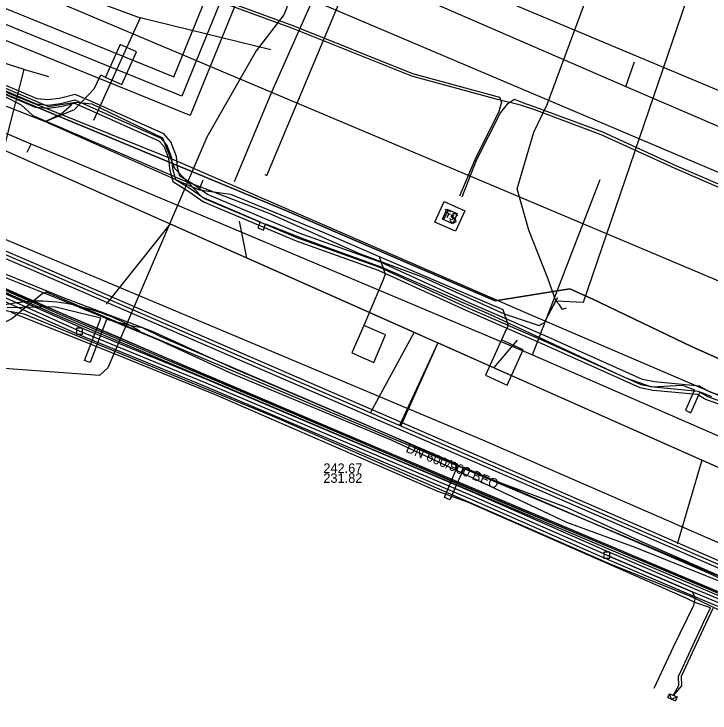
# Model space of a CAD drawing. Extents: x -596024 to -594475, y -1163820 to -1161957.
# Drawn here: x -594674.7 to -594616.3, y -1162272.9 to -1162214.2 of the extents above; entities that cross this region are included whole.
import ezdxf

# ---------------------------------------------------------------- set-up
doc = ezdxf.new("R2010")
doc.units = 0
for name, color, linetype in [('25', 7, 'Continuous'), ('31', 7, 'Continuous'), ('Level 1', 7, 'Continuous'), ('Vrstva 1', 7, 'Continuous'), ('Vrstva 10', 7, 'Continuous'), ('Vrstva 11', 7, 'Continuous'), ('Vrstva 12', 7, 'Continuous'), ('Vrstva 13', 7, 'Continuous'), ('Vrstva 19', 7, 'Continuous'), ('Vrstva 29', 7, 'Continuous'), ('Vrstva 30', 7, 'Continuous'), ('Vrstva 42', 7, 'Continuous'), ('Vrstva 43', 7, 'Continuous'), ('Vrstva 44', 7, 'Continuous'), ('Vrstva 45', 7, 'Continuous'), ('Vrstva 55', 7, 'Continuous'), ('Vrstva 58', 7, 'Continuous'), ('Vrstva 9', 7, 'Continuous')]:
    doc.layers.add(name, color=color, linetype=linetype)

# ---------------------------------------------------------------- blocks, each defined once
blk = doc.blocks.new('NN640')
at = {"layer": '25'}
for points in [[(-1.89, 1.889), (1.889, 1.889)], [(-1.89, -1.89), (-1.89, 1.889)], [(1.889, 1.889), (1.889, -1.89)], [(-1.26, 0.787), (-0.221, 0.787)], [(-0.725, 0.787), (-0.725, -0.788)], [(1.197, 0.661), (0.945, 0.787), (0.661, 0.787), (0.409, 0.661), (0.283, 0.472), (0.283, 0.409), (0.409, 0.22), (1.133, -0.158), (1.259, -0.316), (1.259, -0.473), (1.133, -0.662), (0.913, -0.788), (0.629, -0.788), (0.503, -0.725), (0.283, -0.599)], [(1.889, -1.89), (-1.89, -1.89)]]:
    blk.add_lwpolyline(points, dxfattribs=at)
blk = doc.blocks.new('NN630')
at = {"layer": '31'}
for points in [[(-0.003, -0.7), (-0.703, 0)], [(-0.703, -0.7), (-0.703, 0), (0.697, 0), (0.697, -0.7)], [(-0.003, -0.7), (0.697, 0)], [(-0.703, -0.7), (0.697, -0.7)]]:
    blk.add_lwpolyline(points, dxfattribs=at)
blk = doc.blocks.new('VN640')
at = {"layer": '25'}
for points in [[(-1.89, 1.889), (1.889, 1.889)], [(-1.89, -1.89), (-1.89, 1.889)], [(-1.26, 0.787), (-0.221, 0.787)], [(-0.725, 0.787), (-0.725, -0.788)], [(1.197, 0.661), (0.945, 0.787), (0.661, 0.787), (0.409, 0.661), (0.283, 0.472), (0.283, 0.409), (0.409, 0.22), (1.133, -0.158), (1.259, -0.316), (1.259, -0.473), (1.133, -0.662), (0.913, -0.788), (0.629, -0.788), (0.503, -0.725), (0.283, -0.599)], [(1.889, 1.889), (1.889, -1.89)], [(1.889, -1.89), (-1.89, -1.89)]]:
    blk.add_lwpolyline(points, dxfattribs=at)

msp = doc.modelspace()

# ---------------------------------------------------------------- linework, layer by layer
at = {"layer": 'Level 1'}
for points in [[(-594750.45, -1162195.55), (-594709.77, -1162211.75), (-594681.66, -1162222.95), (-594639.16, -1162241.84), (-594604.2, -1162257.38), (-594561.16, -1162275.84)], [(-594655.18, -1162234.72), (-594655.8, -1162231.63)], [(-594661.62, -1162231.86), (-594666.98, -1162238.6)], [(-594641.16, -1162240.95), (-594644.83, -1162247.74)], [(-594634.45, -1162243.94), (-594632.48, -1162241.63)], [(-594639.16, -1162241.84), (-594642.26, -1162248.81)], [(-594617, -1162251.69), (-594619.08, -1162258.74)]]:
    msp.add_lwpolyline(points, dxfattribs=at)
at = {"layer": 'Vrstva 1'}
msp.add_line((-594639.16, -1162241.84), (-594642.37, -1162248.79), dxfattribs=at)
for points in [[(-594681.66, -1162222.95), (-594661.62, -1162231.86), (-594655.18, -1162234.72), (-594641.16, -1162240.95), (-594639.16, -1162241.84)], [(-594604.2, -1162257.38), (-594609.94, -1162254.83), (-594617, -1162251.69), (-594634.45, -1162243.94), (-594639.16, -1162241.84)]]:
    msp.add_lwpolyline(points, dxfattribs=at)
at = {"layer": 'Vrstva 10'}
for p, q in [((-594642.25, -1162248.515), (-594610.431, -1162262.393)), ((-594610.671, -1162262.943), (-594642.49, -1162249.065))]:
    msp.add_line(p, q, dxfattribs=at)
for points in [[(-594718.121, -1162215.685), (-594682.698, -1162231.026), (-594673.018, -1162235.167), (-594642.251, -1162248.515)], [(-594642.489, -1162249.065), (-594673.256, -1162235.718), (-594682.935, -1162231.577), (-594718.359, -1162216.235)], [(-594669.097, -1162240.596), (-594676.92, -1162237.095), (-594687.944, -1162232.423), (-594698.459, -1162228.081), (-594703.881, -1162225.994), (-594707.851, -1162224.099), (-594708.531, -1162223.765)], [(-594669.343, -1162241.144), (-594677.16, -1162237.645), (-594688.176, -1162232.977), (-594698.681, -1162228.639), (-594704.119, -1162226.546), (-594708.109, -1162224.641), (-594708.769, -1162224.315)], [(-594624.869, -1162259.405), (-594636.251, -1162254.395), (-594658.494, -1162244.943), (-594669.106, -1162240.592)], [(-594625.111, -1162259.955), (-594636.489, -1162254.945), (-594658.726, -1162245.497), (-594669.334, -1162241.148)], [(-594580.255, -1162278.093), (-594603.815, -1162268.273), (-594617.713, -1162262.474), (-594624.153, -1162259.704), (-594624.875, -1162259.403)], [(-594580.485, -1162278.647), (-594604.045, -1162268.827), (-594617.947, -1162263.026), (-594624.387, -1162260.256), (-594625.105, -1162259.957)]]:
    msp.add_lwpolyline(points, dxfattribs=at)
at = {"layer": 'Vrstva 11'}
for points in [[(-594669.47, -1162241.12), (-594668.97, -1162241.12), (-594668.97, -1162240.62), (-594669.47, -1162240.62)], [(-594625.24, -1162259.93), (-594624.74, -1162259.93), (-594624.74, -1162259.43), (-594625.24, -1162259.43)]]:
    msp.add_lwpolyline(points, close=True, dxfattribs=at)
at = {"layer": 'Vrstva 12'}
for points in [[(-594629.27, -1162238.33), (-594629.91, -1162236.5), (-594631.53, -1162232.4), (-594632.5, -1162228.92), (-594631.11, -1162224.16), (-594630, -1162221.85), (-594628.4, -1162217.53), (-594623.66, -1162204.74), (-594619.72, -1162192.17), (-594619.95, -1162191.15), (-594620.564, -1162190.795), (-594621.931, -1162190.178)], [(-594665.75, -1162215.48), (-594673.84, -1162212.04)], [(-594629.27, -1162238.33), (-594626.94, -1162238.42), (-594618.29, -1162213.11)], [(-594701.93, -1162231.57), (-594700.22, -1162232.12), (-594699.53, -1162232.3), (-594698.85, -1162231.48), (-594698.82, -1162230.28), (-594692.89, -1162215.39), (-594692.41, -1162214.76), (-594691.46, -1162214.73), (-594685.17, -1162217.2), (-594675.66, -1162221.09), (-594674.13, -1162221.87), (-594673.14, -1162222.77), (-594660.42, -1162228.26), (-594659.07, -1162228.75), (-594653.33, -1162230.97), (-594645.81, -1162234.32), (-594640.49, -1162236.32), (-594633.61, -1162239.41), (-594630.67, -1162240.39), (-594630.22, -1162240.14), (-594629.84, -1162239.45)], [(-594701.93, -1162231.57), (-594700.22, -1162232.12), (-594699.53, -1162232.3), (-594698.85, -1162231.48), (-594698.82, -1162230.28), (-594692.89, -1162215.39), (-594692.41, -1162214.76), (-594691.46, -1162214.73), (-594685.17, -1162217.2), (-594675.66, -1162221.09), (-594674.13, -1162221.87), (-594673.14, -1162222.77), (-594660.42, -1162228.26), (-594659.07, -1162228.75), (-594653.33, -1162230.97), (-594645.81, -1162234.32), (-594640.49, -1162236.32), (-594633.61, -1162239.41), (-594630.67, -1162240.39), (-594630.22, -1162240.14), (-594629.84, -1162239.45)], [(-594584.85, -1162250), (-594590.2, -1162247.4), (-594665.75, -1162215.48)], [(-594687.5, -1162228.11), (-594635.41, -1162250)], [(-594603.93, -1162268.55), (-594617.83, -1162262.75), (-594624.27, -1162259.98), (-594624.99, -1162259.68), (-594636.37, -1162254.67), (-594658.61, -1162245.22), (-594669.22, -1162240.87), (-594677.04, -1162237.37)], [(-594629.84, -1162239.45), (-594629.1, -1162238.04)], [(-594629.84, -1162239.45), (-594629.27, -1162238.33)], [(-594628.4, -1162238.935), (-594628.69, -1162239.05), (-594628.96, -1162238.67), (-594629.27, -1162238.33)], [(-594635.41, -1162250), (-594584.42, -1162272.21)], [(-594624.99, -1162259.68), (-594624.27, -1162259.98), (-594617.83, -1162262.75), (-594617.57, -1162263.22), (-594617.72, -1162263.9), (-594619.43, -1162267.41), (-594621.03, -1162270.87)], [(-594617.83, -1162262.75), (-594617.57, -1162263.22), (-594617.72, -1162263.9), (-594619.43, -1162267.41), (-594621.03, -1162270.87)]]:
    msp.add_lwpolyline(points, dxfattribs=at)
at = {"layer": 'Vrstva 13'}
for p, q in [((-594649.599, -1162213.102), (-594475.47, -1162287.071)), ((-594673.314, -1162225.133), (-594673.46, -1162225.47)), ((-594673.46, -1162225.47), (-594673.646, -1162225.878)), ((-594631.22, -1162242.86), (-594625.533, -1162228.125))]:
    msp.add_line(p, q, dxfattribs=at)
for points in [[(-594836.23, -1162155.443), (-594836.196, -1162155.782), (-594816.247, -1162164.384), (-594814.935, -1162164.957), (-594803.879, -1162169.64), (-594755.473, -1162190.086), (-594744.01, -1162194.87), (-594731.121, -1162200.339), (-594730.015, -1162200.811), (-594704.47, -1162211.75), (-594699.45, -1162213.94), (-594673.314, -1162225.133)], [(-594653.687, -1162227.711), (-594653.503, -1162227.79), (-594646.352, -1162210.669), (-594640.557, -1162197.047)], [(-594654.732, -1162204.193), (-594543.215, -1162251.024), (-594524.873, -1162258.743), (-594475.47, -1162279.606)], [(-594651.55, -1162212.94), (-594652.09, -1162214.3), (-594654.4, -1162217.32), (-594658.53, -1162224.58), (-594666.86, -1162243.95), (-594667.56, -1162244.58), (-594677.47, -1162243.87), (-594678.66, -1162244.27), (-594679.14, -1162245.09), (-594685.17, -1162257.8), (-594694.88, -1162278.83), (-594696.109, -1162281.678), (-594702.06, -1162295.48), (-594710.48, -1162314.62), (-594714.12, -1162323.47), (-594715.655, -1162327.014), (-594723.77, -1162345.59), (-594733.52, -1162367.83)], [(-594673.314, -1162225.133), (-594670.332, -1162226.359), (-594656.079, -1162232.372), (-594631.22, -1162242.86), (-594605.499, -1162254.07), (-594601.67, -1162255.71)]]:
    msp.add_lwpolyline(points, dxfattribs=at)
at = {"layer": 'Vrstva 19'}
for points in [[(-594695.25, -1162276.17), (-594690.21, -1162265.28), (-594680.2, -1162243.33), (-594679.351, -1162240.241), (-594678.82, -1162238.33), (-594678.078, -1162235.421), (-594674.9, -1162222.97), (-594673.86, -1162218.9), (-594682.15, -1162216.27), (-594693.73, -1162211.66), (-594707.83, -1162205.54), (-594713.34, -1162203.16), (-594714.6, -1162202.61), (-594730.47, -1162196.31), (-594740.5, -1162192.55), (-594751.07, -1162187.95), (-594753.63, -1162189.06), (-594775.09, -1162179.85), (-594776.07, -1162176.84), (-594793.1, -1162168.81), (-594802.09, -1162164.76), (-594816.08, -1162158.49), (-594834.13, -1162150.42), (-594853.67, -1162141.96)], [(-594673.04, -1162199.27), (-594648.07, -1162209.58), (-594623.39, -1162220.33), (-594563.61, -1162246.04), (-594512.61, -1162267.89), (-594494.198, -1162275.805), (-594475.47, -1162283.856)], [(-594648.07, -1162209.58), (-594649.73, -1162213.19), (-594653.1, -1162220.75), (-594656.24, -1162228.33)], [(-594623.39, -1162220.33), (-594622.82, -1162218.73), (-594622.66, -1162218.26)], [(-594673.86, -1162218.9), (-594673.57, -1162218.98)], [(-594673.57, -1162218.98), (-594672.59, -1162219.27), (-594671.82, -1162219.49)], [(-594672.02, -1162237.58), (-594672.39, -1162237.76), (-594674.91, -1162239.83), (-594676.98, -1162240.84), (-594678.73, -1162240.33), (-594678.81, -1162240.31), (-594679.02, -1162240.26), (-594679.43, -1162240.18), (-594679.63, -1162240.15), (-594679.77, -1162240.12), (-594682.47, -1162239.25), (-594684.29, -1162236.54), (-594684.66, -1162235.21), (-594685.53, -1162232.03), (-594685.55, -1162231.56)], [(-594475.47, -1162321.138), (-594483.988, -1162317.438), (-594524.1, -1162300.42), (-594530.74, -1162297.58), (-594538.63, -1162294.19), (-594559.12, -1162285.38), (-594563.88, -1162283.33), (-594564.7, -1162283.08), (-594583.65, -1162275.06), (-594601.81, -1162267.29), (-594608.3, -1162264.51), (-594626.74, -1162256.75), (-594672.02, -1162237.58)]]:
    msp.add_lwpolyline(points, dxfattribs=at)
at = {"layer": 'Vrstva 29'}
msp.add_lwpolyline([(-594527.721, -1162116.547), (-594550.035, -1162144.733), (-594618.49, -1162117.698), (-594660.636, -1162221.142), (-594706.437, -1162202.481)], dxfattribs=at)
at = {"layer": 'Vrstva 30'}
for points in [[(-594706.74, -1162201.008), (-594661.322, -1162219.513), (-594619.181, -1162116.081), (-594550.439, -1162143.229), (-594528.701, -1162115.771)], [(-594526.741, -1162117.323), (-594549.631, -1162146.237), (-594617.799, -1162119.315), (-594659.95, -1162222.771), (-594706.133, -1162203.955)]]:
    msp.add_lwpolyline(points, dxfattribs=at)
at = {"layer": 'Vrstva 42'}
for points in [[(-594841.22, -1162164.89), (-594841.55, -1162165.818), (-594823.941, -1162173.342), (-594805.527, -1162181.255), (-594786.096, -1162189.732), (-594763.998, -1162199.133), (-594752.438, -1162204.617), (-594739.102, -1162210.309), (-594723.16, -1162216.972), (-594709.798, -1162222.556), (-594699.416, -1162226.808), (-594686.936, -1162232.243), (-594670.535, -1162239.442), (-594642.912, -1162251.21), (-594626.307, -1162258.207), (-594595.818, -1162271.123), (-594582.146, -1162276.922), (-594568.678, -1162282.65), (-594548.298, -1162291.531), (-594530.464, -1162298.451), (-594511.972, -1162306.232), (-594493.611, -1162313.902), (-594475.47, -1162321.871)], [(-594805, -1162180.3), (-594805.561, -1162181.567), (-594805.473, -1162181.605), (-594786.214, -1162190.008), (-594764.122, -1162199.407), (-594752.562, -1162204.891), (-594739.218, -1162210.585), (-594723.276, -1162217.248), (-594709.912, -1162222.834), (-594699.532, -1162227.084), (-594687.056, -1162232.517), (-594670.655, -1162239.718), (-594643.03, -1162251.486), (-594626.423, -1162258.483), (-594595.936, -1162271.399), (-594582.264, -1162277.198), (-594568.796, -1162282.926), (-594548.412, -1162291.809), (-594530.576, -1162298.729), (-594512.088, -1162306.508), (-594493.729, -1162314.178), (-594475.47, -1162322.199)], [(-594475.47, -1162322.035), (-594492.486, -1162314.56), (-594509.999, -1162307.221), (-594528.715, -1162299.349), (-594548.355, -1162291.67), (-594568.737, -1162282.788), (-594582.205, -1162277.06), (-594595.877, -1162271.261), (-594626.365, -1162258.345), (-594642.971, -1162251.348), (-594670.595, -1162239.58), (-594686.996, -1162232.38), (-594699.474, -1162226.946), (-594709.855, -1162222.695), (-594723.218, -1162217.11), (-594739.16, -1162210.447), (-594752.5, -1162204.754), (-594764.06, -1162199.27), (-594786.155, -1162189.87), (-594805.5, -1162181.43)], [(-594615.74, -1162262.79), (-594624.65, -1162259.07), (-594637.95, -1162253.48), (-594653.13, -1162246.96), (-594666.17, -1162241.28), (-594679.92, -1162235.52), (-594687.43, -1162232.45), (-594694.39, -1162229.4), (-594701, -1162226.48), (-594711.77, -1162221.9), (-594718.09, -1162219.27), (-594728.65, -1162214.76), (-594737.08, -1162211.18), (-594746.93, -1162206.99), (-594753.92, -1162203.71), (-594761.99, -1162200.35), (-594768.71, -1162197.49), (-594777.63, -1162193.65), (-594785.3, -1162190.25), (-594792.89, -1162187), (-594796.23, -1162185.84), (-594796.51, -1162185.77), (-594796.81, -1162185.85)], [(-594667.01, -1162219.57), (-594665.682, -1162220.163), (-594664.458, -1162217.424), (-594665.828, -1162216.812), (-594667.052, -1162219.551)], [(-594672.114, -1162223.265), (-594669.65, -1162222.26), (-594667.99, -1162220.51), (-594667.45, -1162219.35), (-594667.01, -1162219.57)], [(-594679.89, -1162220.2), (-594674.37, -1162222.37), (-594672.114, -1162223.265)], [(-594672.114, -1162223.265), (-594670.76, -1162222.61), (-594669.89, -1162221.86)], [(-594672.114, -1162223.265), (-594660.02, -1162228.63), (-594659.18, -1162228.99), (-594656.56, -1162229.37), (-594648.72, -1162232.59), (-594644.08, -1162234.6)], [(-594659.18, -1162228.99), (-594658.85, -1162228.16)], [(-594644.08, -1162234.6), (-594643.57, -1162236.08), (-594643.76, -1162236.56)], [(-594644.08, -1162234.6), (-594633.71, -1162239.06)], [(-594643.76, -1162236.56), (-594645.383, -1162240.399), (-594646.369, -1162242.696), (-594644.531, -1162243.485), (-594643.545, -1162241.188), (-594645.383, -1162240.399)], [(-594616.092, -1162264.165), (-594616.71, -1162265.465), (-594618.755, -1162269.87), (-594618.731, -1162270.634), (-594619.409, -1162271.444), (-594618.942, -1162270.611), (-594618.967, -1162269.852), (-594616.892, -1162265.379), (-594616.277, -1162264.09), (-594617.599, -1162263.644), (-594618.337, -1162263.293), (-594636.59, -1162255.243), (-594639.149, -1162254.338), (-594657.807, -1162246.223), (-594668.713, -1162241.784), (-594674.966, -1162239.293)], [(-594633.71, -1162239.06), (-594633.27, -1162240.4), (-594633.53, -1162240.97)], [(-594633.53, -1162240.97), (-594633.821, -1162241.605), (-594635.17, -1162244.562), (-594633.35, -1162245.392), (-594632.001, -1162242.435), (-594633.821, -1162241.605)]]:
    msp.add_lwpolyline(points, dxfattribs=at)
for centre, radius, start, end in [((-594672.585, -1162251.354), 13.003, 81.93145, 108.86849), ((-594673.743, -1162257.133), 18.89, 59.48106, 80.91506)]:
    msp.add_arc(centre, radius, start, end, dxfattribs=at)
at = {"layer": 'Vrstva 44'}
for points in [[(-594615.489, -1162264.329), (-594617.876, -1162263.185), (-594624.753, -1162260.392), (-594653.042, -1162248.004), (-594673.87, -1162239.439), (-594676.32, -1162238.996), (-594700.937, -1162228.271), (-594701.517, -1162227.634), (-594706.4, -1162225.55), (-594708.626, -1162224.544), (-594732.851, -1162213.96), (-594749.58, -1162206.904), (-594751.558, -1162206.159), (-594757.592, -1162203.739), (-594760.561, -1162201.965), (-594774.949, -1162195.637), (-594776.33, -1162195.028), (-594780.641, -1162193.061), (-594785.301, -1162190.858), (-594797.218, -1162185.869), (-594798.27, -1162185.406), (-594820.513, -1162176.019), (-594846.169, -1162165.001), (-594853.363, -1162161.962)], [(-594678.644, -1162205.16), (-594675.8, -1162206.17), (-594668.05, -1162209.23), (-594663.13, -1162210.88), (-594651.32, -1162215.21), (-594641.28, -1162219.24), (-594633.977, -1162221.217), (-594633.824, -1162221.643), (-594634.056, -1162222.424)], [(-594632.138, -1162221.65), (-594632.724, -1162221.408), (-594633.334, -1162221.81), (-594633.914, -1162222.512), (-594635.951, -1162226.531), (-594637.156, -1162229.626)], [(-594632.138, -1162221.65), (-594631.01, -1162222.02), (-594625.35, -1162224.13), (-594619.15, -1162226.98), (-594613.69, -1162229.35), (-594601.89, -1162234.27), (-594599.95, -1162235.68), (-594593.82, -1162238.39), (-594587.39, -1162241.39), (-594581.17, -1162243.85), (-594574.12, -1162246.93), (-594566.25, -1162250.41), (-594548.18, -1162258.19), (-594546.178, -1162259.803)], [(-594634.056, -1162222.424), (-594636.062, -1162226.483), (-594637.354, -1162229.524)], [(-594614.41, -1162261.91), (-594621.99, -1162258.58), (-594628.37, -1162255.68), (-594636.04, -1162252.82), (-594642.94, -1162249.7), (-594656.3, -1162244), (-594663.1, -1162240.9), (-594670.56, -1162238.06), (-594678.56, -1162234.81), (-594686.86, -1162230.99), (-594695.45, -1162227.75), (-594696.12, -1162227.93), (-594696.75, -1162228.24), (-594697.24, -1162228.82), (-594697.77, -1162230.04), (-594699.66, -1162234.68), (-594702.47, -1162240.02), (-594704.27, -1162242.54), (-594705.7, -1162243.65), (-594707.64, -1162244.5), (-594708.77, -1162244.96), (-594709.91, -1162246.4), (-594710.539, -1162247.725)], [(-594710.243, -1162247.851), (-594709.62, -1162246.52), (-594708.65, -1162245.21), (-594707.44, -1162244.71), (-594705.54, -1162243.89), (-594704.05, -1162242.67), (-594702.2, -1162240.18), (-594699.38, -1162234.79), (-594697.5, -1162230.19), (-594696.67, -1162228.8), (-594696.02, -1162228.26), (-594695.41, -1162228.16), (-594695.4, -1162228.15), (-594686.73, -1162231.34), (-594678.69, -1162235.07), (-594670.68, -1162238.26), (-594662.6, -1162241.59), (-594656.44, -1162244.41), (-594643.09, -1162250), (-594636.37, -1162253.13), (-594628.37, -1162256.91), (-594622.62, -1162258.99), (-594614.48, -1162262.29)]]:
    msp.add_lwpolyline(points, dxfattribs=at)
at = {"layer": 'Vrstva 55'}
for points in [[(-594683.22, -1162217.17), (-594671.84, -1162222), (-594669.54, -1162221.63), (-594668.18, -1162221.78), (-594662.26, -1162224.63), (-594661.26, -1162227.18), (-594658.97, -1162229.6), (-594654.07, -1162231.69), (-594654.26, -1162232.2), (-594653.78, -1162232.4), (-594653.63, -1162231.86), (-594650.26, -1162233.18), (-594643.85, -1162235.49), (-594634.88, -1162239.42), (-594623.4, -1162244.78), (-594621.23, -1162245.53), (-594618.62, -1162245.39), (-594617.62, -1162245.78), (-594618.38, -1162247.51), (-594617.94, -1162247.73), (-594617.16, -1162245.97), (-594616.21, -1162246.34)], [(-594609.39, -1162264.46), (-594616.45, -1162261.18), (-594636.96, -1162252.32), (-594638.15, -1162255.02), (-594638.61, -1162254.82), (-594637.45, -1162252.05), (-594662.4, -1162241.34), (-594663.93, -1162240.6), (-594664.66, -1162240.47), (-594666.96, -1162239.89), (-594668.33, -1162243.5), (-594668.8, -1162243.32), (-594667.45, -1162239.77), (-594671.35, -1162238.82), (-594675.31, -1162238.9)]]:
    msp.add_lwpolyline(points, dxfattribs=at)
at = {"layer": 'Vrstva 58'}
for points in [[(-594855.8, -1162145.62), (-594837.62, -1162153.37), (-594836.31, -1162153.98), (-594819.51, -1162161.12), (-594801.35, -1162168.87), (-594799.77, -1162169.48), (-594797.27, -1162170.37), (-594784.28, -1162175.73), (-594782.11, -1162176.71), (-594778.76, -1162179.27), (-594754.53, -1162189.16), (-594752.65, -1162189.31), (-594750.57, -1162189.75), (-594747.53, -1162190.99), (-594651.85, -1162230.77), (-594634.34, -1162238.31), (-594628.08, -1162237.31), (-594627.27, -1162237.69), (-594626.17, -1162238.17), (-594617.89, -1162242.16), (-594607.87, -1162246.62)], [(-594855.521, -1162146.975), (-594837.445, -1162154.525), (-594819.368, -1162162.393), (-594800.867, -1162170.155), (-594782.472, -1162177.705), (-594753.124, -1162190.465), (-594723.671, -1162201.842), (-594694.961, -1162212.9), (-594661.467, -1162226.404), (-594631.163, -1162239.589), (-594604.155, -1162251.18), (-594572.468, -1162264.684), (-594547.693, -1162277.762), (-594525.576, -1162287.119), (-594507.394, -1162294.988), (-594488.786, -1162302.856), (-594475.47, -1162308.493)], [(-594606.25, -1162247.31), (-594607.87, -1162246.62), (-594617.89, -1162242.16), (-594626.17, -1162238.17), (-594627.27, -1162237.69), (-594628.08, -1162237.31), (-594634.34, -1162238.31), (-594651.85, -1162230.77), (-594747.53, -1162190.99), (-594750.57, -1162189.75)], [(-594613.792, -1162229.591), (-594619.257, -1162227.219), (-594625.45, -1162224.372), (-594631.097, -1162222.267), (-594632.22, -1162221.899), (-594634.15, -1162221.404), (-594641.352, -1162219.454), (-594651.401, -1162215.421), (-594663.205, -1162211.093), (-594668.127, -1162209.442), (-594675.879, -1162206.381)], [(-594609.899, -1162248.258), (-594616.365, -1162245.963), (-594617.201, -1162245.497), (-594620.989, -1162245.13), (-594621.991, -1162244.934), (-594630.158, -1162241.262), (-594636.537, -1162238.483), (-594643.91, -1162235.107), (-594650.796, -1162232.645), (-594658.483, -1162229.397), (-594659.666, -1162228.566), (-594660.796, -1162227.867), (-594661.001, -1162227.124), (-594661.083, -1162226.194), (-594661.552, -1162224.965), (-594662.146, -1162224.309), (-594668.429, -1162221.502), (-594669.594, -1162220.993), (-594670.91, -1162221.333), (-594671.877, -1162221.454), (-594672.766, -1162221.374), (-594683.334, -1162216.877)], [(-594683.555, -1162217.532), (-594672.935, -1162222.05), (-594671.865, -1162222.147), (-594670.78, -1162222.011), (-594669.652, -1162221.72), (-594668.707, -1162222.133), (-594662.559, -1162224.879), (-594662.15, -1162225.331), (-594661.761, -1162226.35), (-594661.682, -1162227.247), (-594661.388, -1162228.311), (-594660.046, -1162229.141), (-594658.819, -1162230.003), (-594651.046, -1162233.287), (-594644.17, -1162235.746), (-594636.818, -1162239.112), (-594630.437, -1162241.893), (-594622.201, -1162245.594), (-594621.088, -1162245.813), (-594617.411, -1162246.169), (-594616.65, -1162246.593), (-594610.209, -1162248.879)], [(-594683.47, -1162217.28), (-594672.87, -1162221.79), (-594671.87, -1162221.88), (-594670.83, -1162221.75), (-594669.63, -1162221.44), (-594668.6, -1162221.89), (-594662.4, -1162224.66), (-594661.92, -1162225.19), (-594661.5, -1162226.29), (-594661.42, -1162227.2), (-594661.16, -1162228.14), (-594659.9, -1162228.92), (-594658.69, -1162229.77), (-594650.95, -1162233.04), (-594644.07, -1162235.5), (-594636.71, -1162238.87), (-594630.33, -1162241.65), (-594622.12, -1162245.34), (-594621.05, -1162245.55), (-594617.33, -1162245.91), (-594616.54, -1162246.35), (-594610.09, -1162248.64)], [(-594683.47, -1162217.28), (-594672.87, -1162221.79), (-594671.87, -1162221.88), (-594670.83, -1162221.75), (-594669.63, -1162221.44), (-594668.6, -1162221.89), (-594662.4, -1162224.66), (-594661.92, -1162225.19), (-594661.5, -1162226.29), (-594661.42, -1162227.2), (-594661.16, -1162228.14), (-594659.9, -1162228.92), (-594658.69, -1162229.77), (-594650.95, -1162233.04), (-594644.07, -1162235.5), (-594636.71, -1162238.87), (-594630.33, -1162241.65), (-594622.12, -1162245.34), (-594621.05, -1162245.55), (-594617.33, -1162245.91), (-594616.54, -1162246.35), (-594610.09, -1162248.64)]]:
    msp.add_lwpolyline(points, dxfattribs=at)
at = {"layer": 'Vrstva 9'}
for p, q in [((-594667.318, -1162213.397), (-594664.129, -1162214.572)), ((-594664.129, -1162214.572), (-594668.045, -1162223.188)), ((-594653.177, -1162217.245), (-594664.129, -1162214.572)), ((-594610.551, -1162262.668), (-594642.37, -1162248.79))]:
    msp.add_line(p, q, dxfattribs=at)
msp.add_lwpolyline([(-594642.37, -1162248.79), (-594673.137, -1162235.442), (-594682.817, -1162231.302), (-594718.24, -1162215.96)], dxfattribs=at)

# ---------------------------------------------------------------- block references
at = {"layer": 'Vrstva 43', "xscale": 0.5, "yscale": 0.5}
for name, p, rotation in [('NN640', (-594638.156, -1162231.238), -23.999999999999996), ('NN630', (-594619.409, -1162271.444), -23.00000000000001)]:
    msp.add_blockref(name, p, dxfattribs=dict(at, rotation=rotation))
at = {"layer": 'Vrstva 45', "xscale": 0.25, "yscale": 0.25, "rotation": -23.999999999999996}
msp.add_blockref('VN640', (-594638.156, -1162231.238), dxfattribs=at)

# ---------------------------------------------------------------- texts
at = {"layer": 'Vrstva 12'}
msp.add_text('DN 600/900 BEO', height=0.8, rotation=337.64403, dxfattribs=at).set_placement((-594641.911, -1162250.987))
for s, p in [('242.67', (-594648.766, -1162252.77)), ('231.82', (-594648.766, -1162253.602))]:
    msp.add_text(s, height=0.8, dxfattribs=at).set_placement(p)

doc.saveas('drawing.dxf')
